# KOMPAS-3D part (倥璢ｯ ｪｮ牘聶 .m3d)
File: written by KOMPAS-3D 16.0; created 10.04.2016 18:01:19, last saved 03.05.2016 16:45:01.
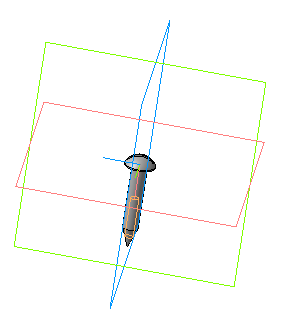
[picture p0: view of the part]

Referenced files in E:\Libs\PartLib\DATA\vault\Methods\Kompas\3D\: PLib_Screw_Shurup_900.m3d
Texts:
  Л63 ГОСТ 15527-2004
  Шуруп 1-3,5x20.3 ГОСТ 1144-80
  head2
  head4
  groove1
  fillet4
  head3
  groove4
  head5
  fillet1
  groove2
  groove3
  fillet2
  groove5
  head1
  (-) Шуруп 1-3,5x20.3 ГОСТ 1144-80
